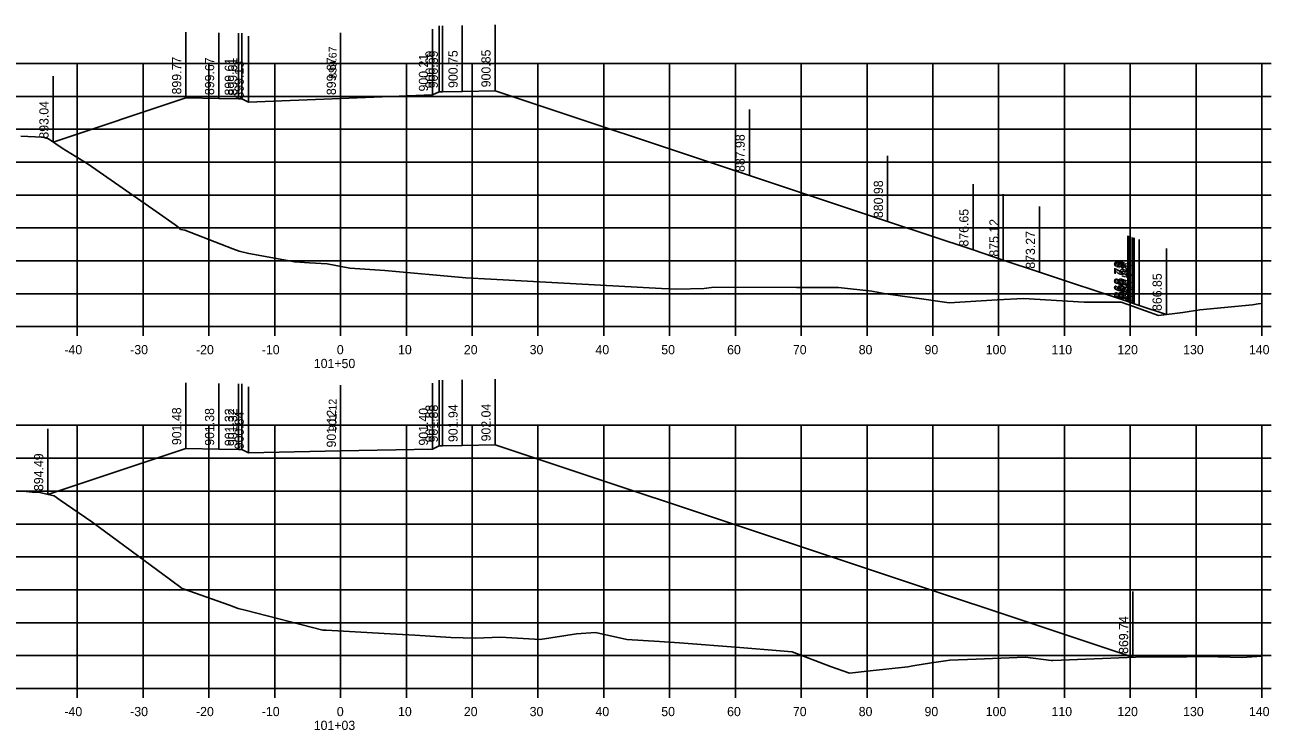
# Model space of a CAD drawing. Extents: x 1098669 to 1198896, y 698679 to 704410.
# Drawn here: x 1112261.2 to 1112450.6, y 701468.9 to 701576.1 of the extents above; entities that cross this region are included whole.
import ezdxf

# ---------------------------------------------------------------- set-up
doc = ezdxf.new("R2010")
doc.units = 0
for name, color, linetype in [('59', 7, 'Continuous'), ('Proposed Surface', 7, 'Continuous'), ('R_Axis', 7, 'Continuous'), ('R_Axis Annot', 7, 'Continuous'), ('R_Fin Surface', 7, 'Continuous'), ('R_Grid', 7, 'Continuous'), ('R_Xsect Elev', 7, 'Continuous')]:
    doc.layers.add(name, color=color, linetype=linetype)

msp = doc.modelspace()

# ---------------------------------------------------------------- linework, layer by layer
at = {"layer": 'Proposed Surface'}
for points in [[(1112260.6, 701559.21), (1112263.84, 701559.05), (1112264.28, 701558.94), (1112264.78, 701558.8), (1112266.89, 701557.38), (1112270.85, 701554.96), (1112281.15, 701547.75), (1112284.03, 701545.71), (1112284.66, 701545.29), (1112284.88, 701545.04), (1112285.53, 701544.94), (1112292.81, 701542.09), (1112293.78, 701541.75), (1112295.24, 701541.38), (1112302.23, 701540.1), (1112304.44, 701539.96), (1112307.13, 701539.82), (1112310.59, 701539.15), (1112315.92, 701538.8), (1112328.24, 701537.67), (1112332.02, 701537.46), (1112357.96, 701536.08), (1112360.21, 701535.94), (1112364.45, 701536.08), (1112365.91, 701536.26), (1112378.46, 701536.23), (1112384.86, 701536.23), (1112389.91, 701535.67), (1112392.04, 701535.27), (1112396.39, 701534.66), (1112401.68, 701533.89), (1112408.96, 701534.31), (1112412.95, 701534.52), (1112422.16, 701534), (1112427.79, 701534), (1112429.53, 701533.35), (1112433.46, 701531.97), (1112437.16, 701532.42), (1112439.74, 701532.81), (1112447.77, 701533.58), (1112448.63, 701533.72), (1112449.18, 701533.8)], [(1112260.96, 701505.24), (1112262.31, 701505.12), (1112263.51, 701505.04), (1112265.43, 701504.58), (1112265.68, 701504.54), (1112266.56, 701503.9), (1112271.4, 701500.6), (1112283.35, 701491.79), (1112285.14, 701490.45), (1112285.27, 701490.4), (1112292.3, 701487.91), (1112293.61, 701487.44), (1112294.7, 701487.16), (1112306.5, 701484.15), (1112306.98, 701484.11), (1112315.81, 701483.63), (1112320.45, 701483.37), (1112325.94, 701482.99), (1112329.71, 701482.93), (1112333.51, 701483.06), (1112339.5, 701482.73), (1112345.06, 701483.56), (1112347.91, 701483.76), (1112352.68, 701482.72), (1112357.67, 701482.4), (1112360.68, 701482.19), (1112369.88, 701481.47), (1112375.99, 701481), (1112377.82, 701480.84), (1112383.62, 701478.6), (1112386.53, 701477.58), (1112389.67, 701477.96), (1112395.39, 701478.58), (1112396.13, 701478.7), (1112398.97, 701479.14), (1112401.12, 701479.48), (1112401.77, 701479.59), (1112405.79, 701479.73), (1112413.24, 701480.01), (1112417.16, 701479.52), (1112417.26, 701479.5), (1112417.44, 701479.51), (1112429.99, 701480.02), (1112437.79, 701480.1), (1112440.08, 701480.13), (1112440.77, 701480.12), (1112446.13, 701479.96), (1112449.18, 701480.17)]]:
    msp.add_lwpolyline(points, dxfattribs=at)
at = {"layer": 'R_Axis'}
for p, q in [((1112449.18, 701530.26), (1112449.18, 701570.26)), ((1112450.58, 701570.26), (1112449.18, 701570.26)), ((1112450.58, 701565.26), (1112449.18, 701565.26)), ((1112450.58, 701560.26), (1112449.18, 701560.26)), ((1112450.58, 701555.26), (1112449.18, 701555.26)), ((1112450.58, 701550.26), (1112449.18, 701550.26)), ((1112450.58, 701545.26), (1112449.18, 701545.26)), ((1112450.58, 701540.26), (1112449.18, 701540.26)), ((1112450.58, 701535.26), (1112449.18, 701535.26)), ((1112169.18, 701530.26), (1112449.18, 701530.26)), ((1112269.18, 701528.86), (1112269.18, 701530.26)), ((1112279.18, 701528.86), (1112279.18, 701530.26)), ((1112289.18, 701528.86), (1112289.18, 701530.26)), ((1112299.18, 701528.86), (1112299.18, 701530.26)), ((1112309.18, 701528.86), (1112309.18, 701530.26)), ((1112319.18, 701528.86), (1112319.18, 701530.26)), ((1112329.18, 701528.86), (1112329.18, 701530.26)), ((1112339.18, 701528.86), (1112339.18, 701530.26)), ((1112349.18, 701528.86), (1112349.18, 701530.26)), ((1112359.18, 701528.86), (1112359.18, 701530.26)), ((1112369.18, 701528.86), (1112369.18, 701530.26)), ((1112379.18, 701528.86), (1112379.18, 701530.26)), ((1112389.18, 701528.86), (1112389.18, 701530.26)), ((1112399.18, 701528.86), (1112399.18, 701530.26)), ((1112409.18, 701528.86), (1112409.18, 701530.26)), ((1112419.18, 701528.86), (1112419.18, 701530.26)), ((1112429.18, 701528.86), (1112429.18, 701530.26)), ((1112439.18, 701528.86), (1112439.18, 701530.26)), ((1112449.18, 701528.86), (1112449.18, 701530.26)), ((1112450.58, 701530.26), (1112449.18, 701530.26)), ((1112449.18, 701475.26), (1112449.18, 701515.26)), ((1112450.58, 701515.26), (1112449.18, 701515.26)), ((1112450.58, 701510.26), (1112449.18, 701510.26)), ((1112450.58, 701505.26), (1112449.18, 701505.26)), ((1112450.58, 701500.26), (1112449.18, 701500.26)), ((1112450.58, 701495.26), (1112449.18, 701495.26)), ((1112450.58, 701490.26), (1112449.18, 701490.26)), ((1112450.58, 701485.26), (1112449.18, 701485.26)), ((1112450.58, 701480.26), (1112449.18, 701480.26)), ((1112169.18, 701475.26), (1112449.18, 701475.26)), ((1112269.18, 701473.86), (1112269.18, 701475.26)), ((1112279.18, 701473.86), (1112279.18, 701475.26)), ((1112289.18, 701473.86), (1112289.18, 701475.26)), ((1112299.18, 701473.86), (1112299.18, 701475.26)), ((1112309.18, 701473.86), (1112309.18, 701475.26)), ((1112319.18, 701473.86), (1112319.18, 701475.26)), ((1112329.18, 701473.86), (1112329.18, 701475.26)), ((1112339.18, 701473.86), (1112339.18, 701475.26)), ((1112349.18, 701473.86), (1112349.18, 701475.26)), ((1112359.18, 701473.86), (1112359.18, 701475.26)), ((1112369.18, 701473.86), (1112369.18, 701475.26)), ((1112379.18, 701473.86), (1112379.18, 701475.26)), ((1112389.18, 701473.86), (1112389.18, 701475.26)), ((1112399.18, 701473.86), (1112399.18, 701475.26)), ((1112409.18, 701473.86), (1112409.18, 701475.26)), ((1112419.18, 701473.86), (1112419.18, 701475.26)), ((1112429.18, 701473.86), (1112429.18, 701475.26)), ((1112439.18, 701473.86), (1112439.18, 701475.26)), ((1112449.18, 701473.86), (1112449.18, 701475.26)), ((1112450.58, 701475.26), (1112449.18, 701475.26))]:
    msp.add_line(p, q, dxfattribs=at)
at = {"layer": 'R_Fin Surface'}
for points in [[(1112265.51, 701558.31), (1112285.68, 701565.03), (1112290.68, 701564.93), (1112293.68, 701564.87), (1112294.18, 701564.87), (1112295.18, 701564.39), (1112309.18, 701564.93), (1112323.18, 701565.48), (1112324.18, 701565.96), (1112324.68, 701565.96), (1112327.68, 701566.02), (1112332.68, 701566.12), (1112371.3, 701553.25), (1112392.31, 701546.24), (1112405.3, 701541.91), (1112409.88, 701540.38), (1112415.41, 701538.54), (1112428.8, 701534.06), (1112428.84, 701534.05), (1112428.95, 701534.01), (1112428.97, 701534.01), (1112429.17, 701533.94), (1112429.2, 701533.93), (1112429.51, 701533.83), (1112429.77, 701533.75), (1112430.54, 701533.49), (1112434.67, 701532.12)], [(1112264.71, 701504.75), (1112285.68, 701511.74), (1112290.68, 701511.64), (1112293.68, 701511.58), (1112294.18, 701511.58), (1112295.18, 701511.1), (1112309.18, 701511.38), (1112323.18, 701511.66), (1112324.18, 701512.14), (1112324.68, 701512.14), (1112327.68, 701512.2), (1112332.68, 701512.3), (1112429.56, 701480.01), (1112429.57, 701480)]]:
    msp.add_lwpolyline(points, dxfattribs=at)
at = {"layer": 'R_Grid'}
for p, q in [((1112169.18, 701570.26), (1112449.18, 701570.26)), ((1112269.18, 701530.26), (1112269.18, 701570.26)), ((1112279.18, 701530.26), (1112279.18, 701570.26)), ((1112289.18, 701530.26), (1112289.18, 701570.26)), ((1112299.18, 701530.26), (1112299.18, 701570.26)), ((1112309.18, 701530.26), (1112309.18, 701570.26)), ((1112319.18, 701530.26), (1112319.18, 701570.26)), ((1112329.18, 701530.26), (1112329.18, 701570.26)), ((1112339.18, 701530.26), (1112339.18, 701570.26)), ((1112349.18, 701530.26), (1112349.18, 701570.26)), ((1112359.18, 701530.26), (1112359.18, 701570.26)), ((1112369.18, 701530.26), (1112369.18, 701570.26)), ((1112379.18, 701530.26), (1112379.18, 701570.26)), ((1112389.18, 701530.26), (1112389.18, 701570.26)), ((1112399.18, 701530.26), (1112399.18, 701570.26)), ((1112409.18, 701530.26), (1112409.18, 701570.26)), ((1112419.18, 701530.26), (1112419.18, 701570.26)), ((1112429.18, 701530.26), (1112429.18, 701570.26)), ((1112439.18, 701530.26), (1112439.18, 701570.26)), ((1112449.18, 701530.26), (1112449.18, 701570.26)), ((1112169.18, 701565.26), (1112449.18, 701565.26)), ((1112169.18, 701560.26), (1112449.18, 701560.26)), ((1112169.18, 701555.26), (1112449.18, 701555.26)), ((1112169.18, 701550.26), (1112449.18, 701550.26)), ((1112169.18, 701545.26), (1112449.18, 701545.26)), ((1112169.18, 701540.26), (1112449.18, 701540.26)), ((1112169.18, 701535.26), (1112449.18, 701535.26)), ((1112169.18, 701530.26), (1112449.18, 701530.26)), ((1112169.18, 701515.26), (1112449.18, 701515.26)), ((1112269.18, 701475.26), (1112269.18, 701515.26)), ((1112279.18, 701475.26), (1112279.18, 701515.26)), ((1112289.18, 701475.26), (1112289.18, 701515.26)), ((1112299.18, 701475.26), (1112299.18, 701515.26)), ((1112309.18, 701475.26), (1112309.18, 701515.26)), ((1112319.18, 701475.26), (1112319.18, 701515.26)), ((1112329.18, 701475.26), (1112329.18, 701515.26)), ((1112339.18, 701475.26), (1112339.18, 701515.26)), ((1112349.18, 701475.26), (1112349.18, 701515.26)), ((1112359.18, 701475.26), (1112359.18, 701515.26)), ((1112369.18, 701475.26), (1112369.18, 701515.26)), ((1112379.18, 701475.26), (1112379.18, 701515.26)), ((1112389.18, 701475.26), (1112389.18, 701515.26)), ((1112399.18, 701475.26), (1112399.18, 701515.26)), ((1112409.18, 701475.26), (1112409.18, 701515.26)), ((1112419.18, 701475.26), (1112419.18, 701515.26)), ((1112429.18, 701475.26), (1112429.18, 701515.26)), ((1112439.18, 701475.26), (1112439.18, 701515.26)), ((1112449.18, 701475.26), (1112449.18, 701515.26)), ((1112169.18, 701510.26), (1112449.18, 701510.26)), ((1112169.18, 701505.26), (1112449.18, 701505.26)), ((1112169.18, 701500.26), (1112449.18, 701500.26)), ((1112169.18, 701495.26), (1112449.18, 701495.26)), ((1112169.18, 701490.26), (1112449.18, 701490.26)), ((1112169.18, 701485.26), (1112449.18, 701485.26)), ((1112169.18, 701480.26), (1112449.18, 701480.26)), ((1112169.18, 701475.26), (1112449.18, 701475.26))]:
    msp.add_line(p, q, dxfattribs=at)
at = {"layer": 'R_Xsect Elev'}
for p, q in [((1112324.18, 701565.96), (1112324.18, 701575.96)), ((1112324.68, 701565.96), (1112324.68, 701575.96)), ((1112327.68, 701566.02), (1112327.68, 701576.02)), ((1112332.68, 701566.12), (1112332.68, 701576.12)), ((1112285.68, 701565.03), (1112285.68, 701575.03)), ((1112290.68, 701564.93), (1112290.68, 701574.93)), ((1112293.68, 701564.87), (1112293.68, 701574.87)), ((1112294.18, 701564.87), (1112294.18, 701574.87)), ((1112295.18, 701564.39), (1112295.18, 701574.39)), ((1112309.18, 701564.93), (1112309.18, 701574.93)), ((1112309.18, 701564.93), (1112309.18, 701574.93)), ((1112323.18, 701565.48), (1112323.18, 701575.48)), ((1112265.51, 701558.31), (1112265.51, 701568.31)), ((1112371.3, 701553.25), (1112371.3, 701563.25)), ((1112392.31, 701546.24), (1112392.31, 701556.24)), ((1112405.3, 701541.91), (1112405.3, 701551.91)), ((1112409.88, 701540.38), (1112409.88, 701550.38)), ((1112415.41, 701538.54), (1112415.41, 701548.54)), ((1112428.8, 701534.06), (1112428.8, 701544.06)), ((1112428.84, 701534.05), (1112428.84, 701544.05)), ((1112428.95, 701534.01), (1112428.95, 701544.01)), ((1112428.97, 701534.01), (1112428.97, 701544.01)), ((1112429.17, 701533.94), (1112429.17, 701543.94)), ((1112429.2, 701533.93), (1112429.2, 701543.93)), ((1112429.51, 701533.83), (1112429.51, 701543.83)), ((1112429.77, 701533.75), (1112429.77, 701543.75)), ((1112430.54, 701533.49), (1112430.54, 701543.49)), ((1112434.67, 701532.12), (1112434.67, 701542.12)), ((1112285.68, 701511.74), (1112285.68, 701521.74)), ((1112290.68, 701511.64), (1112290.68, 701521.64)), ((1112293.68, 701511.58), (1112293.68, 701521.58)), ((1112294.18, 701511.58), (1112294.18, 701521.58)), ((1112295.18, 701511.1), (1112295.18, 701521.1)), ((1112309.18, 701511.38), (1112309.18, 701521.38)), ((1112309.18, 701511.38), (1112309.18, 701521.38)), ((1112323.18, 701511.66), (1112323.18, 701521.66)), ((1112324.18, 701512.14), (1112324.18, 701522.14)), ((1112324.68, 701512.14), (1112324.68, 701522.14)), ((1112327.68, 701512.2), (1112327.68, 701522.2)), ((1112332.68, 701512.3), (1112332.68, 701522.3)), ((1112264.71, 701504.75), (1112264.71, 701514.75)), ((1112429.56, 701480.01), (1112429.56, 701490.01)), ((1112429.57, 701480), (1112429.57, 701490))]:
    msp.add_line(p, q, dxfattribs=at)

# ---------------------------------------------------------------- texts
at = {"layer": '59'}
for s, p in [(' 900.75', (1112326.98, 701566.02)), (' 900.85', (1112331.98, 701566.12)), (' 899.77', (1112284.98, 701565.03)), (' 899.67', (1112289.98, 701564.93)), (' 899.61', (1112292.98, 701564.87)), (' 899.61', (1112293.48, 701564.87)), (' 899.13', (1112294.48, 701564.39)), (' 899.67', (1112308.48, 701564.93)), (' 900.21', (1112322.48, 701565.48)), (' 900.69', (1112323.48, 701565.96)), (' 900.69', (1112323.98, 701565.96)), (' 893.04', (1112264.81, 701558.31)), (' 887.98', (1112370.6, 701553.25)), (' 880.98', (1112391.61, 701546.24)), (' 876.65', (1112404.6, 701541.91)), (' 875.12', (1112409.18, 701540.38)), (' 873.27', (1112414.71, 701538.54)), (' 868.79', (1112428.1, 701534.06)), (' 868.78', (1112428.14, 701534.05)), (' 868.75', (1112428.25, 701534.01)), (' 868.74', (1112428.27, 701534.01)), (' 868.68', (1112428.47, 701533.94)), (' 868.67', (1112428.5, 701533.93)), (' 868.57', (1112428.81, 701533.83)), (' 868.48', (1112429.07, 701533.75)), (' 868.23', (1112429.84, 701533.49)), (' 866.85', (1112433.97, 701532.12)), (' 901.48', (1112284.98, 701511.74)), (' 901.38', (1112289.98, 701511.64)), (' 901.32', (1112292.98, 701511.58)), (' 901.32', (1112293.48, 701511.58)), (' 900.84', (1112294.48, 701511.1)), (' 901.12', (1112308.48, 701511.38)), (' 901.40', (1112322.48, 701511.66)), (' 901.88', (1112323.48, 701512.14)), (' 901.88', (1112323.98, 701512.14)), (' 901.94', (1112326.98, 701512.2)), (' 902.04', (1112331.98, 701512.3)), (' 894.49', (1112264.01, 701504.75)), (' 869.74', (1112428.86, 701480.01)), (' 869.74', (1112428.87, 701480))]:
    msp.add_text(s, height=1.4, rotation=90, dxfattribs=at).set_placement(p)
at = {"layer": 'R_Axis Annot'}
for s, p in [('-40', (1112267.22, 701526.06)), ('-30', (1112277.22, 701526.06)), ('-20', (1112287.22, 701526.06)), ('-10', (1112297.22, 701526.06)), ('0', (1112308.62, 701526.06)), ('10', (1112317.92, 701526.06)), ('20', (1112327.92, 701526.06)), ('30', (1112337.92, 701526.06)), ('40', (1112347.92, 701526.06)), ('50', (1112357.92, 701526.06)), ('60', (1112367.92, 701526.06)), ('70', (1112377.92, 701526.06)), ('80', (1112387.92, 701526.06)), ('90', (1112397.92, 701526.06)), ('100', (1112407.22, 701526.06)), ('110', (1112417.22, 701526.06)), ('120', (1112427.22, 701526.06)), ('130', (1112437.22, 701526.06)), ('140', (1112447.22, 701526.06)), ('101+50', (1112305.12, 701523.96)), ('-40', (1112267.22, 701471.06)), ('-30', (1112277.22, 701471.06)), ('-20', (1112287.22, 701471.06)), ('-10', (1112297.22, 701471.06)), ('0', (1112308.62, 701471.06)), ('10', (1112317.92, 701471.06)), ('20', (1112327.92, 701471.06)), ('30', (1112337.92, 701471.06)), ('40', (1112347.92, 701471.06)), ('50', (1112357.92, 701471.06)), ('60', (1112367.92, 701471.06)), ('70', (1112377.92, 701471.06)), ('80', (1112387.92, 701471.06)), ('90', (1112397.92, 701471.06)), ('100', (1112407.22, 701471.06)), ('110', (1112417.22, 701471.06)), ('120', (1112427.22, 701471.06)), ('130', (1112437.22, 701471.06)), ('140', (1112447.22, 701471.06)), ('101+03', (1112305.11, 701468.96))]:
    msp.add_text(s, height=1.4, dxfattribs=at).set_placement(p)
at = {"layer": 'R_Xsect Elev'}
for s, p in [('899.67', (1112308.58, 701567.93)), ('901.12', (1112308.58, 701514.38))]:
    msp.add_text(s, height=1.2, rotation=90, dxfattribs=at).set_placement(p)

doc.saveas('drawing.dxf')
